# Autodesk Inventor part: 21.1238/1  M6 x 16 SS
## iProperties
Created: 2006-02
Part Number: 21.1238/1  M6 x 16 SS
Material: Stainless Steel
Description: Cylinder Head Cap Screw
Document SubType Name: Modeling
Standard: DIN 7984
Designer: Andy Moles
Standards Organization: DIN
Language: en-US
Size Designation: M6 x 16
Categories: <MemberInstance><Categories><Category DisplayName="Fasteners" InternalName="e4da775c-781d-43d5-af7c-5136215cf5a6" Mnemonic="FSTN"><Category DisplayName="Bolts"
Density: 8.08 g/cm^3
Mass: 5.75352 g
Surface Area: 6.14162 cm^2
Volume: 0.71207 cm^3
Author: Andy Moles
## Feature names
1. Body [Revolution]
2. Slot [Extrusion]
3. Fillet1
4. Chamfer1
